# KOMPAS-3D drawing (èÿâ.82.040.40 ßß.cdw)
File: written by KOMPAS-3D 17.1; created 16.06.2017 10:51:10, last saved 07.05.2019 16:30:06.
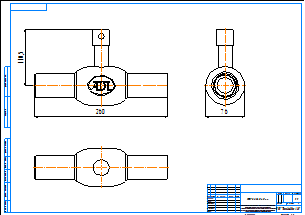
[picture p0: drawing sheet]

Sheet 1: A2, landscape

Title block, sheet 1: name: КШГ.82.040.40 сс; material: Внимание! Данный продукт является объектом авторского права ООО «Торговый Дом АДЛ». / Запрещается изменение, копирование, распространение / (в том числе путем копирования на другие сайты и ресурсы в Интернете) / или любое иное использование информации и объектов без предварительного / согласия правообладателя (ООО «Торговый Дом АДЛ»).; scale: 1:1; sheets: 1; organisation: ООО "Торговый дом АДЛ"; sheet format: A2; stored path: C:\Users\tra\Desktop\2д чертежи\Шаровые краны БИВАЛ\КШ_Бивал_серия_82_85\KOMPAS 2D\КШГ.82.040.40 сс.cdw

Views: Спереди 1, Проекционный вид 2, Проекционный вид 3
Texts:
  Klimkovich
  ADL
Dimensions and other numbers on the sheet: 260; 110,5; 76; 1:1; 1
